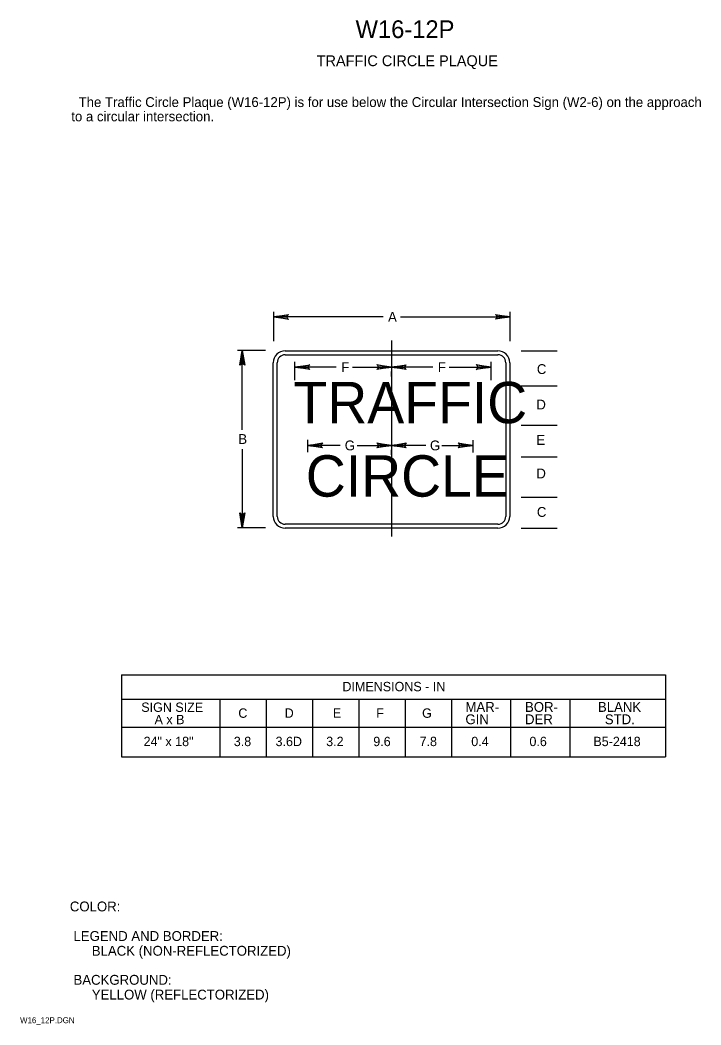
# Model space of a CAD drawing. Extents: x 0.013 to 0.185, y 0.004 to 0.259.
import ezdxf

# ---------------------------------------------------------------- set-up
doc = ezdxf.new("R2010")
doc.units = 0
for name, color, linetype in [('1', 7, 'Continuous'), ('2', 7, 'Continuous'), ('3', 7, 'Continuous')]:
    doc.layers.add(name, color=color, linetype=linetype)

# ---------------------------------------------------------------- blocks, each defined once
blk = doc.blocks.new('RARROW')
at = {"layer": '3'}
for p, q in [((-2.156, 0.285), (-2.2665, 0.384625)), ((-2.2665, 0.384625), (0, 0)), ((0, 0), (-2.2665, -0.379125)), ((-2.156, 0.285), (-2.075625, 0.12075)), ((0, 0), (-2.156, 0.285)), ((-2.14975, -0.2705), (0, 0)), ((-2.075625, 0.12075), (0, 0)), ((0, 0), (-2.074, -0.108)), ((-2.2665, -0.379125), (-2.14975, -0.2705)), ((-2.074, -0.108), (-2.14975, -0.2705))]:
    blk.add_line(p, q, dxfattribs=at)

msp = doc.modelspace()

# ---------------------------------------------------------------- linework, layer by layer
at = {"layer": '3'}
for p, q in [((0.07687, 0.1775), (0.07687, 0.18488)), ((0.10462, 0.18363), (0.07687, 0.18363)), ((0.109, 0.18363), (0.13687, 0.18363)), ((0.13687, 0.1775), (0.13687, 0.18488)), ((0.10675, 0.17763), (0.10675, 0.12788)), ((0.07475, 0.17513), (0.06763, 0.17513)), ((0.06888, 0.15497), (0.06888, 0.17513)), ((0.07975, 0.175), (0.13375, 0.175)), ((0.07975, 0.174), (0.13375, 0.174)), ((0.13962, 0.175), (0.14875, 0.175)), ((0.07675, 0.133), (0.07675, 0.172)), ((0.07775, 0.133), (0.07775, 0.172)), ((0.08224, 0.1676), (0.08224, 0.17223)), ((0.09271, 0.17087), (0.08225, 0.17087)), ((0.09688, 0.17087), (0.10675, 0.17087)), ((0.11725, 0.17087), (0.10675, 0.17087)), ((0.12134, 0.17087), (0.132, 0.17087)), ((0.13204, 0.1676), (0.13204, 0.17223)), ((0.13575, 0.172), (0.13575, 0.133)), ((0.13675, 0.172), (0.13675, 0.133)), ((0.10675, 0.16848), (0.10675, 0.16973)), ((0.13962, 0.16612), (0.14875, 0.16612)), ((0.13962, 0.15613), (0.14875, 0.15613)), ((0.0937, 0.151), (0.0855, 0.151)), ((0.08552, 0.14927), (0.08552, 0.15239)), ((0.09807, 0.151), (0.10675, 0.151)), ((0.11543, 0.151), (0.10675, 0.151)), ((0.11951, 0.151), (0.12748, 0.151)), ((0.12748, 0.14924), (0.12748, 0.15237)), ((0.06888, 0.15006), (0.06888, 0.13012)), ((0.10675, 0.14862), (0.10675, 0.14987)), ((0.13962, 0.14813), (0.14875, 0.14813)), ((0.13962, 0.13787), (0.14875, 0.13787)), ((0.07475, 0.13012), (0.06763, 0.13012)), ((0.13375, 0.131), (0.07975, 0.131)), ((0.13375, 0.13), (0.07975, 0.13)), ((0.13962, 0.13), (0.14875, 0.13)), ((0.03825, 0.09275), (0.17625, 0.09275)), ((0.03825, 0.09275), (0.03825, 0.072)), ((0.17625, 0.09275), (0.17625, 0.072)), ((0.03825, 0.08663), (0.17625, 0.08663)), ((0.06322, 0.08664), (0.06322, 0.072)), ((0.07494, 0.08664), (0.07494, 0.072)), ((0.08669, 0.08664), (0.08669, 0.072)), ((0.09844, 0.08664), (0.09844, 0.072)), ((0.11019, 0.08664), (0.11019, 0.072)), ((0.12197, 0.08664), (0.12197, 0.072)), ((0.13697, 0.08664), (0.13697, 0.072)), ((0.15197, 0.08664), (0.15197, 0.072)), ((0.03825, 0.0795), (0.17625, 0.0795)), ((0.03825, 0.072), (0.17625, 0.072))]:
    msp.add_line(p, q, dxfattribs=at)
for centre, radius, start, end in [((0.07975, 0.172), 0.003, 90, 180), ((0.07975, 0.172), 0.002, 90, 180), ((0.13375, 0.172), 0.003, 0, 90), ((0.13375, 0.172), 0.002, 0, 90), ((0.07975, 0.133), 0.003, 180, 270), ((0.07975, 0.133), 0.002, 180, 270), ((0.13375, 0.133), 0.003, 270, 0), ((0.13375, 0.133), 0.002, 270, 0)]:
    msp.add_arc(centre, radius, start, end, dxfattribs=at)

# ---------------------------------------------------------------- block references
at = {"layer": '3', "xscale": 0.0016545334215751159, "yscale": 0.0016366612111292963}
for p, rotation in [((0.07687, 0.18363), 180), ((0.06888, 0.17513), 90), ((0.08225, 0.17087), 180), ((0.10675, 0.17087), 180), ((0.0855, 0.151), 180), ((0.10675, 0.151), 180), ((0.06888, 0.13012), -90)]:
    msp.add_blockref('RARROW', p, dxfattribs=dict(at, rotation=rotation))
for p in [(0.13687, 0.18363), (0.10675, 0.17087), (0.132, 0.17087), (0.10675, 0.151), (0.12738, 0.151)]:
    msp.add_blockref('RARROW', p, dxfattribs=at)

# ---------------------------------------------------------------- texts
at = {"layer": '1'}
for s, height, p in [('W16-12P', 0.0045, (0.09763, 0.25438)), ('TRAFFIC CIRCLE PLAQUE', 0.0027503, (0.08775, 0.24725)), ('COLOR:', 0.0025, (0.02513, 0.03275)), (' LEGEND AND BORDER:', 0.0024998, (0.02513, 0.02525)), ('      BLACK (NON-REFLECTORIZED)', 0.0024998, (0.02513, 0.0215)), (' BACKGROUND:', 0.0024998, (0.02513, 0.01413)), ('      YELLOW (REFLECTORIZED)', 0.0024998, (0.02513, 0.01038)), ('W16_12P.DGN', 0.0015, (0.0125, 0.00438))]:
    msp.add_text(s, height=height, dxfattribs=at).set_placement(p)
at = {"layer": '2'}
for s, height, p in [('  The Traffic Circle Plaque (W16-12P) is for use below the Circular Intersection Sign (W2-6) on the approach', 0.00249975, (0.0255, 0.23688)), ('to a circular intersection.', 0.0024998, (0.0255, 0.23325))]:
    msp.add_text(s, height=height, dxfattribs=at).set_placement(p)
at = {"layer": '3'}
for s, height, p in [('A', 0.0025, (0.10587, 0.18238)), ('F', 0.0025, (0.094, 0.16962)), ('F', 0.0025, (0.1185, 0.16962)), ('C', 0.0025, (0.14363, 0.16912)), ('TRAFFIC', 0.0105, (0.08188, 0.15663)), ('D', 0.0025, (0.1435, 0.16012)), ('B', 0.0025, (0.06788, 0.15138)), ('E', 0.0025, (0.1435, 0.15113)), ('G ', 0.0025, (0.09488, 0.14975)), ('G ', 0.0025, (0.1165, 0.14975)), ('CIRCLE', 0.0105, (0.085, 0.138)), ('D', 0.0025, (0.1435, 0.14263)), ('C', 0.0025, (0.14363, 0.13287)), ('DIMENSIONS - IN', 0.0023752, (0.09429, 0.08862)), ('SIGN SIZE', 0.002375, (0.04325, 0.08338)), ('C', 0.00238, (0.06788, 0.08188)), ('D', 0.00238, (0.07963, 0.08188)), ('E', 0.00238, (0.09187, 0.08188)), ('F', 0.00238, (0.10288, 0.08188)), ('G', 0.00238, (0.1145, 0.08188)), ('MAR-', 0.0025, (0.1255, 0.08338)), ('BOR-', 0.0025, (0.14062, 0.08338)), ('BLANK', 0.0025, (0.15913, 0.08338)), ('A x B', 0.002375, (0.04662, 0.08025)), ('GIN', 0.0025, (0.1255, 0.08025)), ('DER', 0.0025, (0.14062, 0.08025)), ('STD.', 0.0025, (0.16087, 0.08025)), ('24" x 18"', 0.002375, (0.04384, 0.07469)), ('3.8', 0.002375, (0.06673, 0.07469)), ('3.6D', 0.002375, (0.07732, 0.07469)), ('3.2', 0.002375, (0.09017, 0.07469)), ('9.6', 0.002375, (0.10212, 0.07469)), ('7.8', 0.002375, (0.11386, 0.07469)), ('0.4', 0.002375, (0.12698, 0.07469)), ('0.6', 0.002375, (0.14174, 0.07469)), ('B5-2418', 0.002375, (0.15796, 0.07469))]:
    msp.add_text(s, height=height, dxfattribs=at).set_placement(p)

doc.saveas('drawing.dxf')
